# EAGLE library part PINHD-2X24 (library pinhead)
PIN HEADER
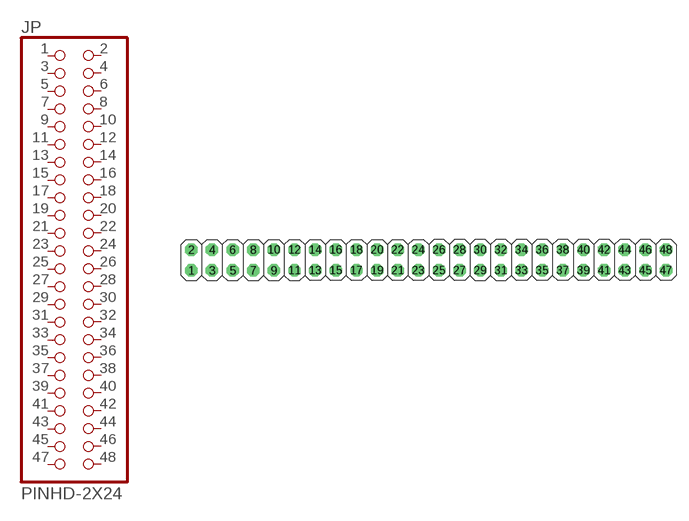
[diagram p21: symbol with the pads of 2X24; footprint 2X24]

Designator prefix JP

## PINHD-2X24  [2X24]
1  1  pas
2  2  pas
3  3  pas
4  4  pas
5  5  pas
6  6  pas
7  7  pas
8  8  pas
9  9  pas
10  10  pas
11  11  pas
12  12  pas
13  13  pas
14  14  pas
15  15  pas
16  16  pas
17  17  pas
18  18  pas
19  19  pas
20  20  pas
21  21  pas
22  22  pas
23  23  pas
24  24  pas
25  25  pas
26  26  pas
27  27  pas
28  28  pas
29  29  pas
30  30  pas
31  31  pas
32  32  pas
33  33  pas
34  34  pas
35  35  pas
36  36  pas
37  37  pas
38  38  pas
39  39  pas
40  40  pas
41  41  pas
42  42  pas
43  43  pas
44  44  pas
45  45  pas
46  46  pas
47  47  pas
48  48  pas

## Footprint 2X24 (pad centres in mm)
PIN HEADER
drill 1.016 octagon: 1 -27.94,-1.27; 2 -27.94,1.27; 3 -25.4,-1.27; 4 -25.4,1.27; 5 -22.86,-1.27; 6 -22.86,1.27; 7 -20.32,-1.27; 8 -20.32,1.27; 9 -17.78,-1.27; 10 -17.78,1.27; 11 -15.24,-1.27; 12 -15.24,1.27; 13 -12.7,-1.27; 14 -12.7,1.27; 15 -10.16,-1.27; 16 -10.16,1.27; 17 -7.62,-1.27; 18 -7.62,1.27; 19 -5.08,-1.27; 20 -5.08,1.27; 21 -2.54,-1.27; 22 -2.54,1.27; 23 0,-1.27; 24 0,1.27; 25 2.54,-1.27; 26 2.54,1.27; 27 5.08,-1.27; 28 5.08,1.27; 29 7.62,-1.27; 30 7.62,1.27; 31 10.16,-1.27; 32 10.16,1.27; 33 12.7,-1.27; 34 12.7,1.27; 35 15.24,-1.27; 36 15.24,1.27; 37 17.78,-1.27; 38 17.78,1.27; 39 20.32,-1.27; 40 20.32,1.27; 41 22.86,-1.27; 42 22.86,1.27; 43 25.4,-1.27; 44 25.4,1.27; 45 27.94,-1.27; 46 27.94,1.27; 47 30.48,-1.27; 48 30.48,1.27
